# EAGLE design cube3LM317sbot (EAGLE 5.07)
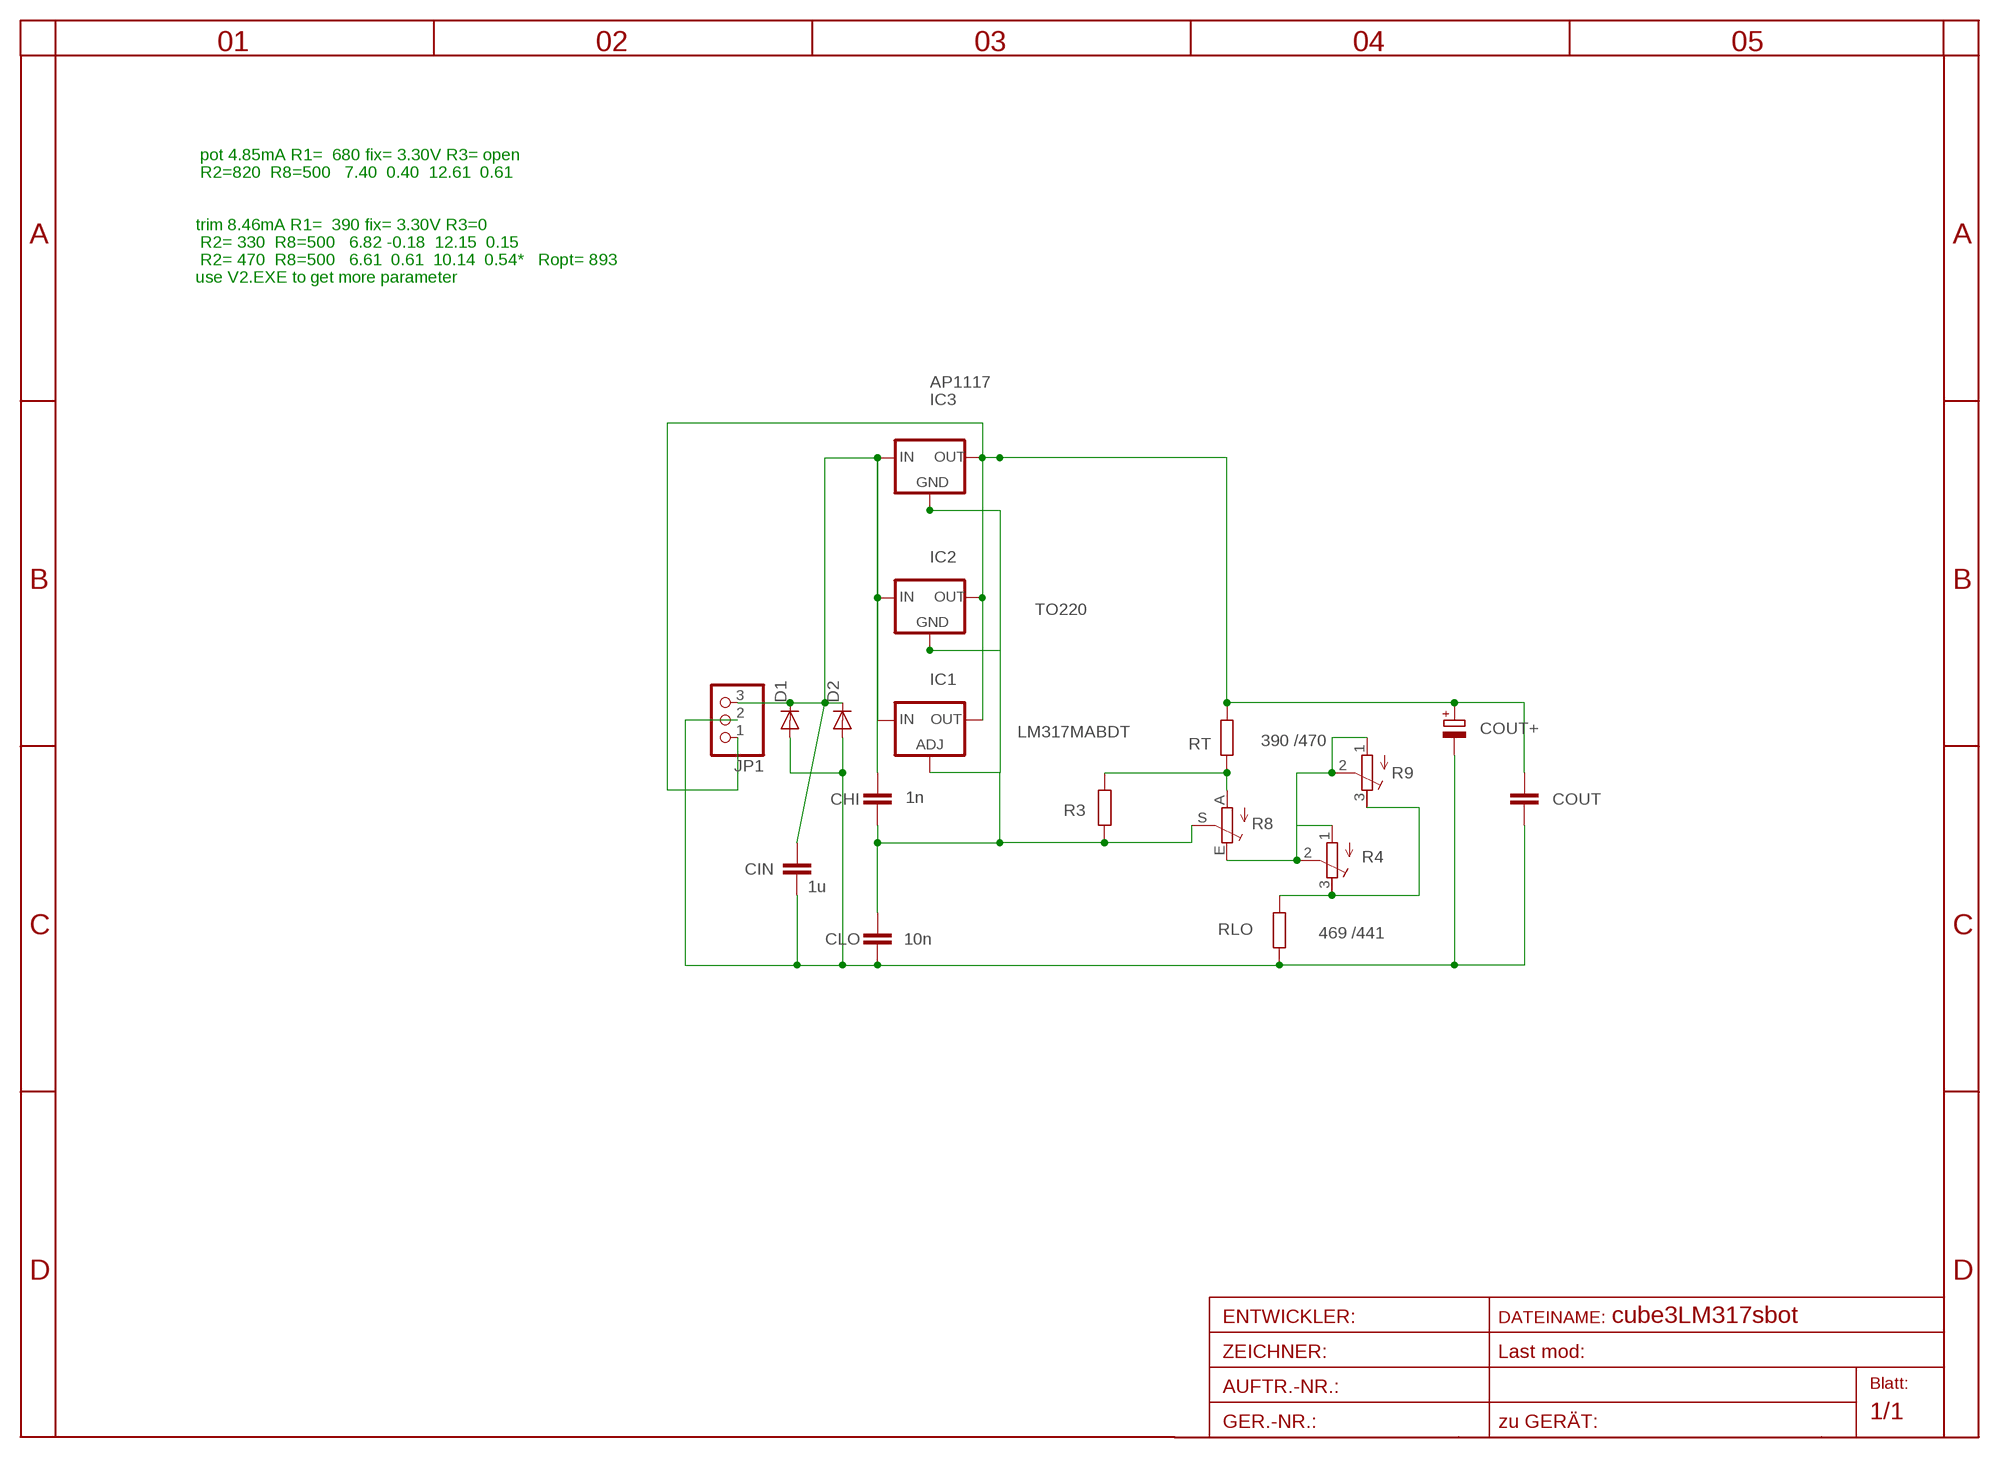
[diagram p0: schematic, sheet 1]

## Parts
CHI  1n  C-EUC0805  [C0805]
CIN  1u  C-EUC1206  [C1206]
CLO  10n  C-EUC0805  [C0805]
COUT  C-EUC1206  [C1206]
COUT+  CPOL-EUE2.5-6  [E2,5-6]
D1  DIODE-MINIMELF  [MINIMELF]
D2  DIODE-MINIMELF  [MINIMELF]
IC1  LM317MABDT  [DPACK]
IC2  TO220  78XXS  [78XXS]
IC3  AP1117  [SOT223]
JP1  PINHD-1X3  [1X03]
R3  R-EU_R0603  [R0603]
R4  R-TRIMM3202  [RTRIM3202]
R8  TRIM_EU-RAND160  [RANDL]
R9  R-TRIMM3374  [RTRIM3374]
RLO  469 /441  R-EU_R1206  [R1206]
RT  390 /470  R-EU_R1206  [R1206]

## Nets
GND: CIN.2 CLO.2 COUT+.- COUT.2 D1.A D2.A JP1.2 RLO.1
IN: CHI.1 CIN.1 D1.C D2.C IC1.3(IN) IC2.IN IC3.3(IN) JP1.3
N$1: R4.1(E) R4.2(S) R8.E R9.1(E) R9.2(S)
N$4: CHI.2 CLO.1 IC1.1(ADJ) IC2.GND IC3.1(GND) R3.1 R8.S
N$6: R4.3(A) R9.3(A) RLO.2
N$7: R3.2 R8.A RT.1
OUT: COUT+.+ COUT.1 IC1.4(OUT) IC2.OUT IC3.2(OUT) IC3.4(TAB) JP1.1 RT.2

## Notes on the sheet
- pot 4.85mA R1=  680 fix= 3.30V R3= open
- R2=820  R8=500   7.40  0.40  12.61  0.61
- trim 8.46mA R1=  390 fix= 3.30V R3=0
- R2= 330  R8=500   6.82 -0.18  12.15  0.15
- R2= 470  R8=500   6.61  0.61  10.14  0.54*   Ropt= 893
- use V2.EXE to get more parameter

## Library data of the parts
CHI CIN CLO COUT = rcl:C-EU: CAPACITOR, European symbol
COUT+ = rcl:CPOL-EU: POLARIZED CAPACITOR, European symbol
D1 D2 = diode-1:DIODE-: DIODE
IC1 = v-reg:LM317?*: 500 mA Adjustable Output Positive Voltage Regulator Source: http://www.onsemi.co.jp .. LM317M-D.PDF
IC2 = v-reg:78XXS: VOLTAGE REGULATOR
IC3 = v-reg:AP1117
JP1 = pinhead:PINHD-1X3: PIN HEADER
R3 RLO RT = rcl:R-EU_: RESISTOR, European symbol
R4 R9 = rcl:R-TRIMM: Trimm resistor
R8 = pot:TRIM_EU-: POTENTIOMETER

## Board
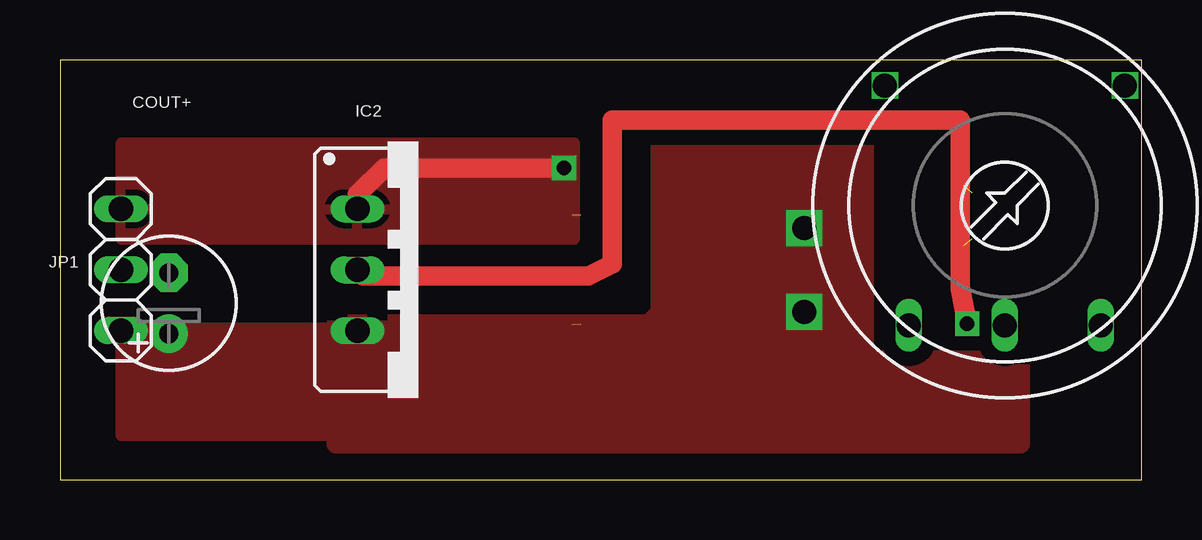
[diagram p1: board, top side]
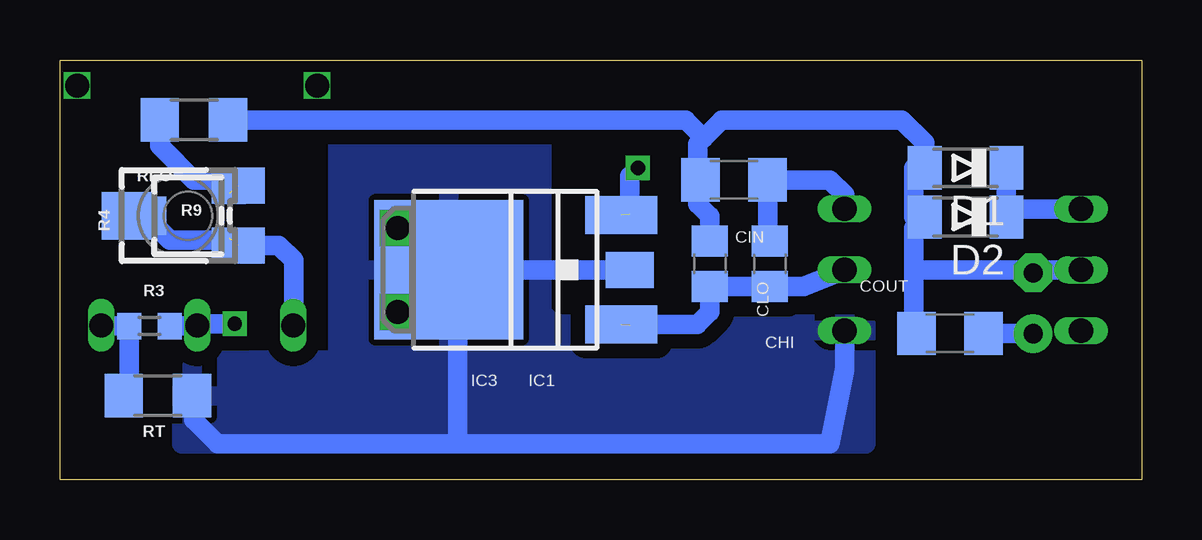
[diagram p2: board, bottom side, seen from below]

Size 45.08 x 17.5 mm. Coordinates in mm from the lower left corner, seen from the top.
Outline: 0,0 45.08,0 45.08,17.5 0,17.5 0,0
Copper layers (1*16): Top 0.035mm / dielectric 1.5mm / Bottom 0.035mm
Design rules "default": minimum track width 10mil, minimum drill 20mil, track to track 8mil, track to pad 8mil, pad to pad 8mil, via to via 8mil, smd to smd 8mil, copper to edge 40mil, drill to drill 8mil, minimum pad ring 1mil, minimum via ring 8mil, stop-mask expansion 4mil, vias tented up to drill 0mil, thermal gap 10mil

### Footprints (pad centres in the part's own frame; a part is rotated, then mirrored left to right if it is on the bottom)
C0805 = smd 1.3 x 1.5: 1 -0.95,0; 2 0.95,0
C1206 = smd 1.6 x 1.8: 1 -1.4,0; 2 1.4,0
E2,5-6 = drill 0.8 pad 1.6 round: + -1.27,0 | drill 0.8 pad 1.6 octagon: - 1.27,0
MINIMELF = smd 1.4 x 1.8: A 1.7,0; C -1.7,0
DPACK = smd 1.6 x 3: 1 -2.28,-4.8; 3 2.28,-4.8 | smd 5.8 x 6.2: 4 0,2.38
78XXS = drill 1.016 long: GND 0,-2.54; IN -2.54,-2.54; OUT 2.54,-2.54
SOT223 = smd 1.5 x 2: 1 -2.3,-3.15; 2 0,-3.15; 3 2.3,-3.15 | smd 3.8 x 2: 4 0,3.15
1X03 = drill 1.016 long: 1 -2.54,0; 2 0,0; 3 2.54,0
R0603 = smd 1 x 1.1: 1 -0.85,0; 2 0.85,0
RTRIM3202 = smd 0.9 x 1.3: 1 -0.95,-1.75; 3 0.95,-1.75 | smd 1.6 x 1.4: 2 0,1.6
RANDL = drill 1 long: A -4,5; E 4,5; S 0,5 | drill 1 square: P$1 -5,-5; P$2 5,-5
RTRIM3374 = smd 1.5 x 2.2: 1 -1.25,-2.5; 3 1.25,-2.5 | smd 1.98 x 2.17: 2 0,2.1
R1206 = smd 1.6 x 1.803: 1 -1.422,0; 2 1.422,0

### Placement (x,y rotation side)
CHI  15.5,9 270 bottom
CIN  17,12.5 180 bottom
CLO  18,9 90 bottom
COUT  8,6.1 180 bottom
COUT+  4.53,7.35 90 top
D1  7.35,13 180 bottom
D2  7.35,10.95 180 bottom
IC1  26.5,8.75 90 bottom
IC2  14.93,8.75 270 top
IC3  24.5,8.75 90 bottom
JP1  2.54,8.75 90 top
R3  41.35,6.4 180 bottom
R4  39.75,11 90 bottom
R8  39.37,11.43 180 top
R9  40.15,11.01 90 bottom
RLO  39.5,15 180 bottom
RT  41,3.5 0 bottom

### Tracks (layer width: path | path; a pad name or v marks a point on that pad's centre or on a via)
GND
  Bottom 0.813: 4.53,8.75 JP1.2 | COUT+.- 4.53,8.75 | CLO.2 18,11 18.5,11.5 18.5,12.6 | COUT.2 9.5,6.1 9.5,9 | 9.5,9 9.5,10.5 9.05,10.5 D2.A 9.5,10.95 9.5,13 D1.A 9.05,14.05 10,15 17.5,15 18.25,14.25 | 18.25,14.25 18.5,14 18.5,12.6 | 18.5,12.6 CIN.2 | RLO.1 19,15 18.25,14.25 | 4.53,8.75 9.25,8.75 9.5,9
IN  (via drill 0.6)  (1 unrouted)
  Top 0.813: v21,13 13.5,13 12.39,11.89 IC2.IN
  Bottom 0.813: IC2.IN 12.39,11.89 13,12.5 CIN.1 15.6,10.05 CHI.1 | IC3.3 21.35,12.65 v21,13 | JP1.3 5.31,11.29 D2.C D1.C
  pour Top (isolate 0.305): 21.44,14.06 21.44,10 2.54,10 2.54,14.06
N$1  (1 unrouted)
  Bottom 0.813: R9.2 R4.2 41.35,10.85 40.5,10 38.05,10 R4.1 | R9.1 35.96,9.76 35.35,9.15 35.35,6.45 R8.E
N$4  (via drill 0.6)  (1 unrouted)
  Top 0.813: v37.8,6.5 37.5,8 37.5,15 23,15 23,9 22,8.5 12.64,8.5 IC2.GND
  Bottom 0.813: v37.8,6.5 39,6.5 R8.S 39.4,6.4 R3.1 | IC2.GND 14.09,8.05 CHI.2 CLO.1 18,7 18.53,6.47 IC1.1
N$6  (1 unrouted)
  Bottom 0.813: R9.3 37.49,12.42 | RLO.2 40.92,13.92 39.5,12.5 38.55,12.5 R4.3
N$7
  Bottom 0.813: R8.A 43.34,6.4 R3.2 42.2,3.72 RT.1
OUT  (via drill 1)
  Bottom 0.813: IC2.OUT 12.39,4.61 13,1.5 28.5,1.5 | 28.5,8.37 IC1.4 | 28.5,8.37 28.5,2.5 28.5,1.5 | 28.5,1.5 38.5,1.5 39.5,2.5 39.5,3.42 RT.2 | 28.5,8.37 28.03,8.37 IC3.4 IC3.2 | COUT.1 4.55,6.1 COUT+.+
  other vias: 31,10.5 31,7
  pour Top (isolate 0.61, no thermals): 2.54,6.35 20.01,6.35 20.01,1.81 2.54,1.81
  pour Bottom (isolate 0.61): 25,14 33.5,14 33.5,5 40,5 40,1.5 11.5,1.5 11.5,6.5 24.5,6.5 25,7
  pour Top (isolate 0.61): 25,14 33.5,14 33.5,5 40,5 40,1.5 11.5,1.5 11.5,6.5 24.5,6.5 25,7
